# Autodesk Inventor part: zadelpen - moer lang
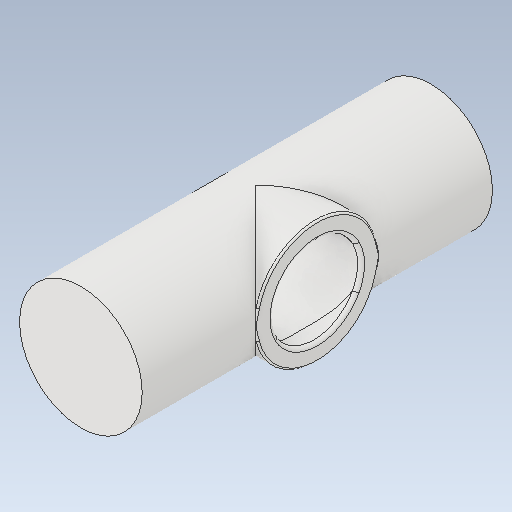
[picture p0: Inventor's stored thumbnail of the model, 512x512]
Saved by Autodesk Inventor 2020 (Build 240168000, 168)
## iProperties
Created: 2017-11
Part Number: zadelpen - moer lang
Material: Ogólny
Document SubType Name: Modeling
Designer: Tomasz
Density: 1 g/cm^3
Appearance: Domyślna
Author: Tomasz
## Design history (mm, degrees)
feature "Solid1"
node "Bryła1"
